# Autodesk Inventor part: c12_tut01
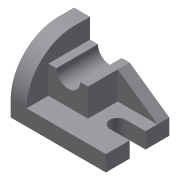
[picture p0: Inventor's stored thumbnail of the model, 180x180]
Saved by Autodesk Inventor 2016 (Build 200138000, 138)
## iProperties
Shininess: 77.0
Length Units: 11269
Angle Units: 11279
Time Units: 11290
Mass Units: 11283
Length Display Precision: 3
Angle Display Precision: 2
Created: 2001-11
Part Number: c12_tut01
Document SubType Name: Modeling
Designer: Renu Muthoo
Density: 1 g/cm^3
Material: Generic
Appearance: Default
Density: 0.0
Volumn: 0.0
Area: 0.0
PropertySet Name: Model Information
Control State: 0
Master: False
Checked Out: False
Author: Renu Muthoo
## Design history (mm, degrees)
sketch "Sketch1"
  geometry: L1 (-48, 36)-(48, 36); L2 (48, -28)-(-48, -28); L3 (-48, -28)-(-48, 36); L4 (48, 12)-(28, 12); L5 (28, -4)-(48, -4); L6 (48, 36)-(48, 12); L7 (48, -4)-(48, -28); A1 r 8 centre (28, 4) between (28, 12) and (28, -4)
  constraints: 14 end point, 4 parallel, 3 perpendicular, 2 point on circle, 2 tangent, 1 centre point, 1 collinear, 1 horizontal
  dimensions: "d0" = 96 distance of L2.start L2.end; "d1" = 64 distance of L2.end L1.start; "d2" = 20 distance of L4.start L4.end; "d3" = 24 distance between parallel lines of L2 L5; "d4" = 16 distance between parallel lines of L4 L5
extrude "Extrusion1" new body sketch "Sketch1" distance "d5" = 16; taper "d6" = 0 deg
sketch "Sketch2"
  geometry: L1 (16, 64)-(64, 64); L2 (64, 64)-(64, 48); L3 (16, 0)-(16, 0); L4 (16, 0)-(16, 64); L5 (0, 64)-(16, 64) reference; L6 (16, 0)-(16, 64) reference; L7 (0, 0)-(16, 0) reference; L8 (0, 0)-(0, 64) reference; A1 r 48 centre (16, 48) between (16, 0) and (64, 48)
  constraints: 8 end point, 3 collinear, 3 perpendicular, 2 point on circle, 2 tangent, 1 centre point, 1 horizontal
  dimensions: "d7" = 64 distance between parallel lines of L2 L8; "d8" = 48 radius of A1
extrude "Extrusion2" join sketch "Sketch2" distance "d9" = 16; taper "d10" = 0 deg
sketch "Sketch3"
  geometry: L1 (16, -44)-(16, -16); L2 (16, -16)-(56, -16); L3 (56, -16)-(56, -44); L4 (56, -44)-(48, -44); L5 (24, -44)-(16, -44); L6 (16, -64)-(16, -16) reference; L7 (16, -16)-(96, -16) reference; A1 r 12 centre (36, -44) between (48, -44) and (24, -44)
  constraints: 10 end point, 3 collinear, 3 parallel, 2 equal length, 2 point on circle, 1 centre point, 1 perpendicular, 1 point on line, 1 vertical
  dimensions: "d11" = 28 distance of L2.end L3.end; "d12" = 8 distance of L3.end L4.end; "d13" = 24 distance of L5.start L4.end
extrude "Extrusion3" join sketch "Sketch3" distance "d14" = 42; taper "d15" = 0 deg
sketch "Sketch4"
  geometry: L1 (56, -16)-(96, -16) reference; L2 (56, -16)-(56, -44) reference; L3 (96, -16)-(56, -44)
  constraints: 2 end point
extrude "Extrusion4" join sketch "Sketch4" distance "d16" = 12; taper "d17" = 0 deg
body "Solid1"
